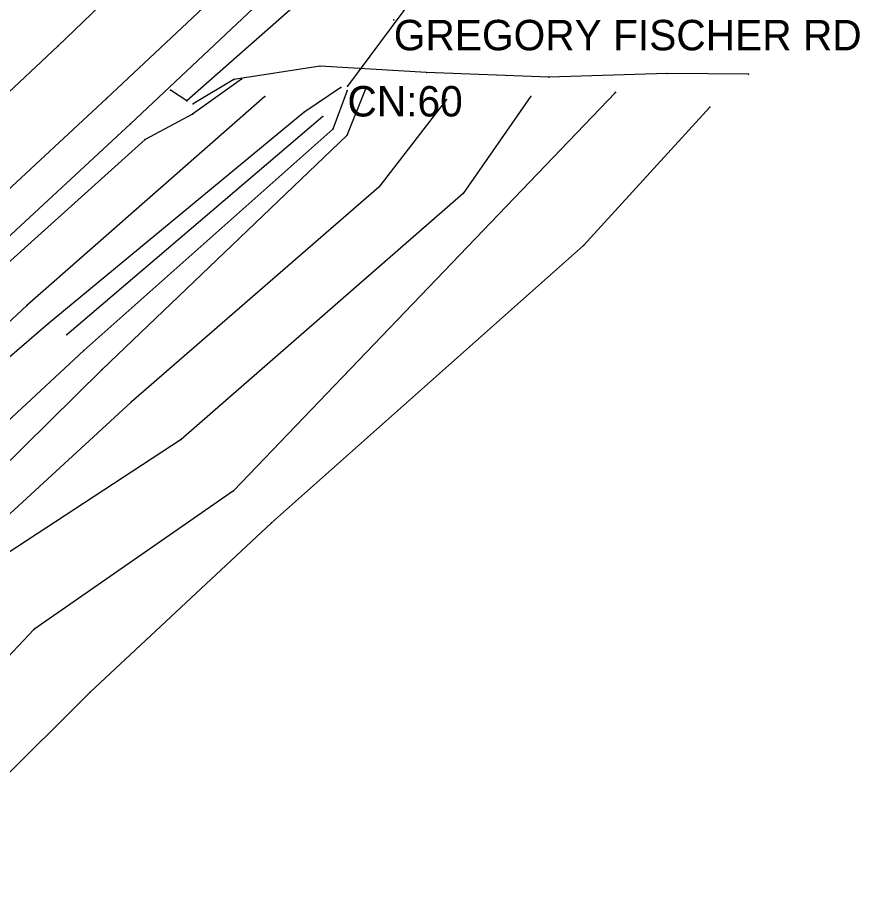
# Model space of a CAD drawing. Extents: x 1419505 to 1434054, y 1956910 to 1968644.
# Drawn here: x 1432681.8 to 1432820.3, y 1967111.6 to 1967253.6 of the extents above; entities that cross this region are included whole.
import ezdxf

# ---------------------------------------------------------------- set-up
doc = ezdxf.new("R2010")
doc.units = 0
for name, color, linetype in [('S_BREAKLINE', 7, 'Continuous'), ('S_DITCHLINE', 7, 'Continuous'), ('S_DRG_PT_SYM', 7, 'Continuous'), ('S_EDGE_PAVEMENT', 7, 'Continuous'), ('S_GRAVEL_ROAD', 7, 'Continuous'), ('S_GRD_PT_SYM', 7, 'Continuous'), ('S_MSC_PT_SYM', 7, 'Continuous'), ('S_PAVEMENT_CROWN', 7, 'Continuous'), ('S_RDW_PT_SYM', 7, 'Continuous'), ('S_SHOULDER', 7, 'Continuous'), ('S_SIDE_DRAIN', 7, 'Continuous'), ('S_SIDE_DRAIN_ANNOT', 7, 'Continuous'), ('S_SURVEY_TEXT_ANNOT', 7, 'Continuous')]:
    doc.layers.add(name, color=color, linetype=linetype)

msp = doc.modelspace()

# ---------------------------------------------------------------- linework, layer by layer
at = {"layer": 'S_BREAKLINE'}
for p, q in [((1432718.6915, 1967243.4526), (1432710.603, 1967237.7212)), ((1432780.1075, 1967241.2805), (1432717.3735, 1967175.8202)), ((1432739.0889, 1967241.9555), (1432735.9517, 1967234.187)), ((1432780.1035, 1967241.3475), (1432780.1075, 1967241.2805)), ((1432722.4978, 1967240.6014), (1432683.3903, 1967206.2832)), ((1432752.3317, 1967240.1044), (1432741.212, 1967225.6935)), ((1432766.2426, 1967240.6374), (1432755.1099, 1967224.6754)), ((1432795.6385, 1967238.8463), (1432774.8642, 1967216.1489)), ((1432732.0514, 1967237.3362), (1432689.9397, 1967201.4749)), ((1432710.603, 1967237.7212), (1432702.8185, 1967233.551)), ((1432735.9517, 1967234.187), (1432695.7681, 1967195.7405)), ((1432702.8185, 1967233.551), (1432671.1125, 1967205.0171)), ((1432741.212, 1967225.6935), (1432700.5314, 1967190.4132)), ((1432755.1099, 1967224.6754), (1432708.7459, 1967184.2758)), ((1432774.8642, 1967216.1489), (1432723.5809, 1967170.5819)), ((1432683.3903, 1967206.2832), (1432653.4303, 1967178.4864)), ((1432695.7681, 1967195.7405), (1432666.2962, 1967166.6937)), ((1432700.5314, 1967190.4132), (1432671.7145, 1967163.9195)), ((1432708.7459, 1967184.2758), (1432674.5747, 1967161.9113)), ((1432717.3735, 1967175.8202), (1432684.5443, 1967153.0358)), ((1432723.5809, 1967170.5819), (1432693.7989, 1967142.7271)), ((1432684.5443, 1967153.0358), (1432654.0264, 1967120.8287)), ((1432693.7989, 1967142.7271), (1432662.3989, 1967111.5991))]:
    msp.add_line(p, q, dxfattribs=at)
at = {"layer": 'S_DITCHLINE'}
for p, q in [((1432734.9696, 1967242.0895), (1432728.8912, 1967237.9653)), ((1432736.0567, 1967241.5735), (1432733.6875, 1967235.2291)), ((1432728.8912, 1967237.9653), (1432686.8685, 1967203.28)), ((1432733.6875, 1967235.2291), (1432692.7679, 1967198.8857)), ((1432686.8685, 1967203.28), (1432655.8315, 1967176.4353)), ((1432692.7679, 1967198.8857), (1432662.4429, 1967170.9099))]:
    msp.add_line(p, q, dxfattribs=at)
at = {"layer": 'S_DRG_PT_SYM'}
msp.add_lwpolyline([(1432736.0767, 1967242.3275), (1432736.0767, 1967242.3775), (1432736.0767, 1967242.3275), (1432736.0267, 1967242.3275), (1432736.0767, 1967242.3275), (1432736.0767, 1967242.2775), (1432736.0767, 1967242.3275), (1432736.1267, 1967242.3275)], dxfattribs=at)
at = {"layer": 'S_EDGE_PAVEMENT'}
for p, q in [((1432726.9551, 1967268.9663), (1432696.4981, 1967240.2604)), ((1432696.4981, 1967240.2604), (1432664.7191, 1967210.7975))]:
    msp.add_line(p, q, dxfattribs=at)
at = {"layer": 'S_GRAVEL_ROAD'}
for p, q in [((1432731.5674, 1967245.6068), (1432717.4005, 1967243.4226)), ((1432749.0655, 1967244.5777), (1432731.5674, 1967245.6068)), ((1432769.1818, 1967243.7596), (1432749.0655, 1967244.5777)), ((1432788.6231, 1967244.4057), (1432769.1818, 1967243.7596)), ((1432801.9979, 1967244.2667), (1432788.6231, 1967244.4057)), ((1432717.4005, 1967243.4226), (1432710.743, 1967239.4134))]:
    msp.add_line(p, q, dxfattribs=at)
at = {"layer": 'S_GRD_PT_SYM'}
for points in [[(1432718.6915, 1967243.4526), (1432718.6915, 1967243.5026), (1432718.6915, 1967243.4526), (1432718.6415, 1967243.4526), (1432718.6915, 1967243.4526), (1432718.6915, 1967243.4026), (1432718.6915, 1967243.4526), (1432718.7415, 1967243.4526)], [(1432734.9696, 1967242.0895), (1432734.9696, 1967242.1395), (1432734.9696, 1967242.0895), (1432734.9196, 1967242.0895), (1432734.9696, 1967242.0895), (1432734.9696, 1967242.0395), (1432734.9696, 1967242.0895), (1432735.0196, 1967242.0895)], [(1432736.0567, 1967241.5735), (1432736.0567, 1967241.6235), (1432736.0567, 1967241.5735), (1432736.0067, 1967241.5735), (1432736.0567, 1967241.5735), (1432736.0567, 1967241.5235), (1432736.0567, 1967241.5735), (1432736.1067, 1967241.5735)], [(1432739.0889, 1967241.9555), (1432739.0889, 1967242.0055), (1432739.0889, 1967241.9555), (1432739.0389, 1967241.9555), (1432739.0889, 1967241.9555), (1432739.0889, 1967241.9055), (1432739.0889, 1967241.9555), (1432739.1389, 1967241.9555)], [(1432780.1035, 1967241.3475), (1432780.1035, 1967241.3975), (1432780.1035, 1967241.3475), (1432780.0535, 1967241.3475), (1432780.1035, 1967241.3475), (1432780.1035, 1967241.2975), (1432780.1035, 1967241.3475), (1432780.1535, 1967241.3475)], [(1432780.1075, 1967241.2805), (1432780.1075, 1967241.3305), (1432780.1075, 1967241.2805), (1432780.0575, 1967241.2805), (1432780.1075, 1967241.2805), (1432780.1075, 1967241.2305), (1432780.1075, 1967241.2805), (1432780.1575, 1967241.2805)], [(1432722.4978, 1967240.6014), (1432722.4978, 1967240.6514), (1432722.4978, 1967240.6014), (1432722.4478, 1967240.6014), (1432722.4978, 1967240.6014), (1432722.4978, 1967240.5514), (1432722.4978, 1967240.6014), (1432722.5478, 1967240.6014)], [(1432752.3317, 1967240.1044), (1432752.3317, 1967240.1544), (1432752.3317, 1967240.1044), (1432752.2817, 1967240.1044), (1432752.3317, 1967240.1044), (1432752.3317, 1967240.0544), (1432752.3317, 1967240.1044), (1432752.3817, 1967240.1044)], [(1432766.2426, 1967240.6374), (1432766.2426, 1967240.6874), (1432766.2426, 1967240.6374), (1432766.1926, 1967240.6374), (1432766.2426, 1967240.6374), (1432766.2426, 1967240.5874), (1432766.2426, 1967240.6374), (1432766.2926, 1967240.6374)], [(1432795.6385, 1967238.8463), (1432795.6385, 1967238.8963), (1432795.6385, 1967238.8463), (1432795.5885, 1967238.8463), (1432795.6385, 1967238.8463), (1432795.6385, 1967238.7963), (1432795.6385, 1967238.8463), (1432795.6885, 1967238.8463)], [(1432710.603, 1967237.7212), (1432710.603, 1967237.7712), (1432710.603, 1967237.7212), (1432710.553, 1967237.7212), (1432710.603, 1967237.7212), (1432710.603, 1967237.6712), (1432710.603, 1967237.7212), (1432710.653, 1967237.7212)], [(1432728.8912, 1967237.9653), (1432728.8912, 1967238.0153), (1432728.8912, 1967237.9653), (1432728.8412, 1967237.9653), (1432728.8912, 1967237.9653), (1432728.8912, 1967237.9153), (1432728.8912, 1967237.9653), (1432728.9412, 1967237.9653)], [(1432732.0514, 1967237.3362), (1432732.0514, 1967237.3862), (1432732.0514, 1967237.3362), (1432732.0014, 1967237.3362), (1432732.0514, 1967237.3362), (1432732.0514, 1967237.2862), (1432732.0514, 1967237.3362), (1432732.1014, 1967237.3362)], [(1432733.6875, 1967235.2291), (1432733.6875, 1967235.2791), (1432733.6875, 1967235.2291), (1432733.6375, 1967235.2291), (1432733.6875, 1967235.2291), (1432733.6875, 1967235.1791), (1432733.6875, 1967235.2291), (1432733.7375, 1967235.2291)], [(1432735.9517, 1967234.187), (1432735.9517, 1967234.237), (1432735.9517, 1967234.187), (1432735.9017, 1967234.187), (1432735.9517, 1967234.187), (1432735.9517, 1967234.137), (1432735.9517, 1967234.187), (1432736.0017, 1967234.187)], [(1432702.8185, 1967233.551), (1432702.8185, 1967233.601), (1432702.8185, 1967233.551), (1432702.7685, 1967233.551), (1432702.8185, 1967233.551), (1432702.8185, 1967233.501), (1432702.8185, 1967233.551), (1432702.8685, 1967233.551)], [(1432741.212, 1967225.6935), (1432741.212, 1967225.7435), (1432741.212, 1967225.6935), (1432741.162, 1967225.6935), (1432741.212, 1967225.6935), (1432741.212, 1967225.6435), (1432741.212, 1967225.6935), (1432741.262, 1967225.6935)], [(1432755.1099, 1967224.6754), (1432755.1099, 1967224.7254), (1432755.1099, 1967224.6754), (1432755.0599, 1967224.6754), (1432755.1099, 1967224.6754), (1432755.1099, 1967224.6254), (1432755.1099, 1967224.6754), (1432755.1599, 1967224.6754)], [(1432774.8642, 1967216.1489), (1432774.8642, 1967216.1989), (1432774.8642, 1967216.1489), (1432774.8142, 1967216.1489), (1432774.8642, 1967216.1489), (1432774.8642, 1967216.0989), (1432774.8642, 1967216.1489), (1432774.9142, 1967216.1489)], [(1432683.3903, 1967206.2832), (1432683.3903, 1967206.3332), (1432683.3903, 1967206.2832), (1432683.3403, 1967206.2832), (1432683.3903, 1967206.2832), (1432683.3903, 1967206.2332), (1432683.3903, 1967206.2832), (1432683.4403, 1967206.2832)], [(1432686.8685, 1967203.28), (1432686.8685, 1967203.33), (1432686.8685, 1967203.28), (1432686.8185, 1967203.28), (1432686.8685, 1967203.28), (1432686.8685, 1967203.23), (1432686.8685, 1967203.28), (1432686.9185, 1967203.28)], [(1432689.9397, 1967201.4749), (1432689.9397, 1967201.5249), (1432689.9397, 1967201.4749), (1432689.8897, 1967201.4749), (1432689.9397, 1967201.4749), (1432689.9397, 1967201.4249), (1432689.9397, 1967201.4749), (1432689.9897, 1967201.4749)], [(1432692.7679, 1967198.8857), (1432692.7679, 1967198.9357), (1432692.7679, 1967198.8857), (1432692.7179, 1967198.8857), (1432692.7679, 1967198.8857), (1432692.7679, 1967198.8357), (1432692.7679, 1967198.8857), (1432692.8179, 1967198.8857)], [(1432695.7681, 1967195.7405), (1432695.7681, 1967195.7905), (1432695.7681, 1967195.7405), (1432695.7181, 1967195.7405), (1432695.7681, 1967195.7405), (1432695.7681, 1967195.6905), (1432695.7681, 1967195.7405), (1432695.8181, 1967195.7405)], [(1432700.5314, 1967190.4132), (1432700.5314, 1967190.4632), (1432700.5314, 1967190.4132), (1432700.4814, 1967190.4132), (1432700.5314, 1967190.4132), (1432700.5314, 1967190.3632), (1432700.5314, 1967190.4132), (1432700.5814, 1967190.4132)], [(1432708.7459, 1967184.2758), (1432708.7459, 1967184.3258), (1432708.7459, 1967184.2758), (1432708.6959, 1967184.2758), (1432708.7459, 1967184.2758), (1432708.7459, 1967184.2258), (1432708.7459, 1967184.2758), (1432708.7959, 1967184.2758)], [(1432717.3735, 1967175.8202), (1432717.3735, 1967175.8702), (1432717.3735, 1967175.8202), (1432717.3235, 1967175.8202), (1432717.3735, 1967175.8202), (1432717.3735, 1967175.7702), (1432717.3735, 1967175.8202), (1432717.4235, 1967175.8202)], [(1432723.5809, 1967170.5819), (1432723.5809, 1967170.6319), (1432723.5809, 1967170.5819), (1432723.5309, 1967170.5819), (1432723.5809, 1967170.5819), (1432723.5809, 1967170.5319), (1432723.5809, 1967170.5819), (1432723.6309, 1967170.5819)], [(1432684.5443, 1967153.0358), (1432684.5443, 1967153.0858), (1432684.5443, 1967153.0358), (1432684.4943, 1967153.0358), (1432684.5443, 1967153.0358), (1432684.5443, 1967152.9858), (1432684.5443, 1967153.0358), (1432684.5943, 1967153.0358)], [(1432693.7989, 1967142.7271), (1432693.7989, 1967142.7771), (1432693.7989, 1967142.7271), (1432693.7489, 1967142.7271), (1432693.7989, 1967142.7271), (1432693.7989, 1967142.6771), (1432693.7989, 1967142.7271), (1432693.8489, 1967142.7271)]]:
    msp.add_lwpolyline(points, dxfattribs=at)
at = {"layer": 'S_MSC_PT_SYM'}
msp.add_lwpolyline([(1432743.6932, 1967253.1992), (1432743.6932, 1967253.2492), (1432743.6932, 1967253.1992), (1432743.6432, 1967253.1992), (1432743.6932, 1967253.1992), (1432743.6932, 1967253.1492), (1432743.6932, 1967253.1992), (1432743.7432, 1967253.1992)], dxfattribs=at)
at = {"layer": 'S_PAVEMENT_CROWN'}
for p, q in [((1432718.8886, 1967278.1859), (1432688.4756, 1967248.882)), ((1432688.4756, 1967248.882), (1432656.4325, 1967218.923))]:
    msp.add_line(p, q, dxfattribs=at)
at = {"layer": 'S_RDW_PT_SYM'}
for points in [[(1432688.4756, 1967248.882), (1432688.4756, 1967248.932), (1432688.4756, 1967248.882), (1432688.4256, 1967248.882), (1432688.4756, 1967248.882), (1432688.4756, 1967248.832), (1432688.4756, 1967248.882), (1432688.5256, 1967248.882)], [(1432731.5674, 1967245.6068), (1432731.5674, 1967245.6568), (1432731.5674, 1967245.6068), (1432731.5174, 1967245.6068), (1432731.5674, 1967245.6068), (1432731.5674, 1967245.5568), (1432731.5674, 1967245.6068), (1432731.6174, 1967245.6068)], [(1432749.0655, 1967244.5777), (1432749.0655, 1967244.6277), (1432749.0655, 1967244.5777), (1432749.0155, 1967244.5777), (1432749.0655, 1967244.5777), (1432749.0655, 1967244.5277), (1432749.0655, 1967244.5777), (1432749.1155, 1967244.5777)], [(1432788.6231, 1967244.4057), (1432788.6231, 1967244.4557), (1432788.6231, 1967244.4057), (1432788.5731, 1967244.4057), (1432788.6231, 1967244.4057), (1432788.6231, 1967244.3557), (1432788.6231, 1967244.4057), (1432788.6731, 1967244.4057)], [(1432801.9979, 1967244.2667), (1432801.9979, 1967244.3167), (1432801.9979, 1967244.2667), (1432801.9479, 1967244.2667), (1432801.9979, 1967244.2667), (1432801.9979, 1967244.2167), (1432801.9979, 1967244.2667), (1432802.0479, 1967244.2667)], [(1432717.4005, 1967243.4226), (1432717.4005, 1967243.4726), (1432717.4005, 1967243.4226), (1432717.3505, 1967243.4226), (1432717.4005, 1967243.4226), (1432717.4005, 1967243.3726), (1432717.4005, 1967243.4226), (1432717.4505, 1967243.4226)], [(1432769.1818, 1967243.7596), (1432769.1818, 1967243.8096), (1432769.1818, 1967243.7596), (1432769.1318, 1967243.7596), (1432769.1818, 1967243.7596), (1432769.1818, 1967243.7096), (1432769.1818, 1967243.7596), (1432769.2318, 1967243.7596)], [(1432706.9898, 1967241.6265), (1432706.9898, 1967241.6765), (1432706.9898, 1967241.6265), (1432706.9398, 1967241.6265), (1432706.9898, 1967241.6265), (1432706.9898, 1967241.5765), (1432706.9898, 1967241.6265), (1432707.0398, 1967241.6265)], [(1432696.4981, 1967240.2604), (1432696.4981, 1967240.3104), (1432696.4981, 1967240.2604), (1432696.4481, 1967240.2604), (1432696.4981, 1967240.2604), (1432696.4981, 1967240.2104), (1432696.4981, 1967240.2604), (1432696.5481, 1967240.2604)], [(1432709.692, 1967239.9074), (1432709.692, 1967239.9574), (1432709.692, 1967239.9074), (1432709.642, 1967239.9074), (1432709.692, 1967239.9074), (1432709.692, 1967239.8574), (1432709.692, 1967239.9074), (1432709.742, 1967239.9074)], [(1432710.743, 1967239.4134), (1432710.743, 1967239.4634), (1432710.743, 1967239.4134), (1432710.693, 1967239.4134), (1432710.743, 1967239.4134), (1432710.743, 1967239.3634), (1432710.743, 1967239.4134), (1432710.793, 1967239.4134)], [(1432700.4054, 1967236.1191), (1432700.4054, 1967236.1691), (1432700.4054, 1967236.1191), (1432700.3554, 1967236.1191), (1432700.4054, 1967236.1191), (1432700.4054, 1967236.0691), (1432700.4054, 1967236.1191), (1432700.4554, 1967236.1191)]]:
    msp.add_lwpolyline(points, dxfattribs=at)
at = {"layer": 'S_SHOULDER'}
for p, q in [((1432731.8844, 1967265.7391), (1432700.4054, 1967236.1191)), ((1432731.7904, 1967259.4666), (1432709.692, 1967239.9074)), ((1432709.692, 1967239.9074), (1432706.9898, 1967241.6265)), ((1432700.4054, 1967236.1191), (1432669.0553, 1967207.0513))]:
    msp.add_line(p, q, dxfattribs=at)
at = {"layer": 'S_SIDE_DRAIN'}
msp.add_line((1432754.0738, 1967266.5191), (1432736.0767, 1967242.3275), dxfattribs=at)

# ---------------------------------------------------------------- texts
at = {"layer": 'S_SIDE_DRAIN_ANNOT'}
msp.add_text('CN:60', height=5, dxfattribs=at).set_placement((1432736.0767, 1967237.3275))
at = {"layer": 'S_SURVEY_TEXT_ANNOT'}
msp.add_text('GREGORY FISCHER RD', height=5, dxfattribs=at).set_placement((1432743.6932, 1967248.1992))

doc.saveas('drawing.dxf')
